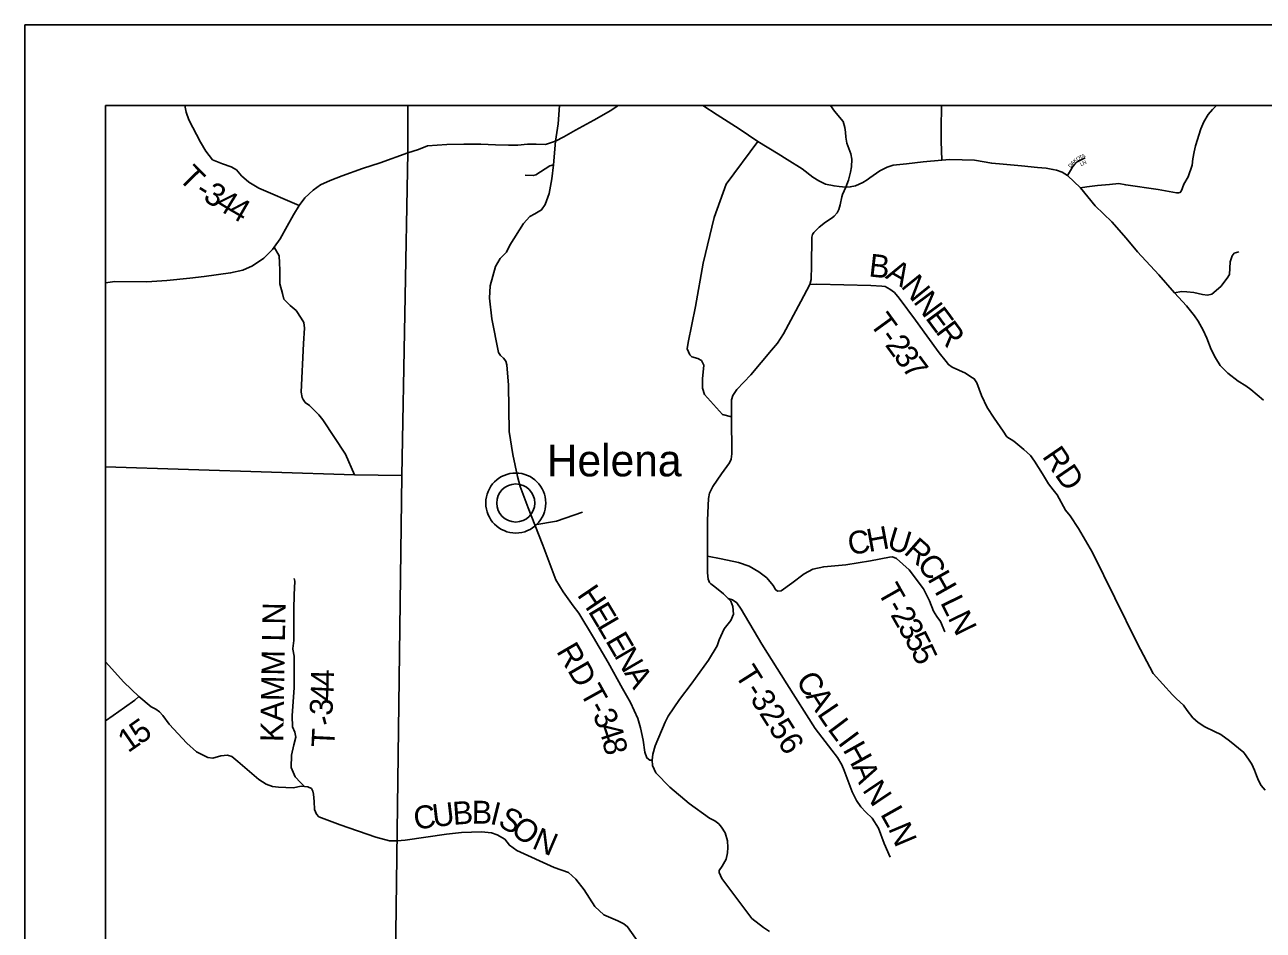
# Model space of a CAD drawing. Extents: x -22 to 431, y -18 to 160.
# Drawn here: x 319.355 to 322.427, y 157.874 to 160.12 of the extents above; entities that cross this region are included whole.
import ezdxf

# ---------------------------------------------------------------- set-up
doc = ezdxf.new("R2010")
doc.units = 0
for name, color, linetype in [('GM_X_Adjacent_County', 7, 'Continuous'), ('GM_X_Adjacent_County_Text', 7, 'Continuous'), ('GM_X_City_Street', 7, 'Continuous'), ('GM_X_City_Street_Text', 7, 'Continuous'), ('GM_X_County_Road', 7, 'Continuous'), ('GM_X_County_ROW', 7, 'Continuous'), ('GM_X_County_Subdivision', 7, 'Continuous'), ('GM_X_Major_River_Text', 7, 'Continuous'), ('GM_X_Minor_River_Text', 7, 'Continuous'), ('GM_X_Section', 7, 'Continuous'), ('GM_X_Township_Road', 7, 'Continuous'), ('GM_X_Township_ROW', 7, 'Continuous')]:
    doc.layers.add(name, color=color, linetype=linetype)

msp = doc.modelspace()

# ---------------------------------------------------------------- linework, layer by layer
at = {"layer": 'GM_X_Adjacent_County_Text'}
for points in [[(321.3912, 159.7168), (321.3982, 159.7343), (321.4032, 159.754), (321.4058, 159.7677), (321.4061, 159.7864), (321.4038, 159.7995), (321.3938, 159.8264), (321.3912, 159.8413), (321.3906, 159.8535), (321.3892, 159.8653), (321.3848, 159.8797), (321.3635, 159.9054), (321.3533, 159.9199)], [(320.9114, 158.2958), (320.9126, 158.3105), (320.9187, 158.331), (320.9431, 158.39), (320.951, 158.4051), (320.9791, 158.4459), (321.0076, 158.4841), (321.0508, 158.5438), (321.0721, 158.579), (321.0775, 158.5941), (321.0893, 158.6217), (321.1059, 158.6422), (321.1124, 158.6577), (321.1114, 158.677), (321.1061, 158.6903), (321.0992, 158.697), (321.0877, 158.7082), (321.0666, 158.7257), (321.0568, 158.7329), (321.053, 158.7363), (321.05, 158.7447), (321.0485, 158.7606), (321.0486, 158.8015), (321.0486, 158.891), (321.0507, 158.9448), (321.0534, 158.9584), (321.0613, 158.9747), (321.083, 159.0057), (321.1027, 159.0333), (321.1073, 159.0427), (321.1088, 159.056), (321.1078, 159.1478), (321.1074, 159.1894), (321.1112, 159.2004), (321.1214, 159.2148), (321.1555, 159.2514), (321.2071, 159.313), (321.2216, 159.3301), (321.2366, 159.3531), (321.2796, 159.4337), (321.3018, 159.4755), (321.3056, 159.4883), (321.3061, 159.5229), (321.3073, 159.5927), (321.309, 159.5993), (321.3122, 159.6047), (321.3252, 159.6179), (321.3409, 159.6302), (321.3576, 159.6412), (321.3628, 159.6453), (321.3699, 159.6536), (321.3737, 159.6616), (321.3773, 159.6733), (321.3815, 159.6931), (321.3832, 159.6986), (321.3912, 159.7168)], [(320.2612, 158.0954), (320.2598, 158.0954), (320.2255, 158.1044), (320.1373, 158.1353), (320.0843, 158.1549), (320.0783, 158.1614), (320.0737, 158.1735), (320.0723, 158.1933), (320.0712, 158.2115), (320.0693, 158.2191), (320.0659, 158.2251), (320.0569, 158.2297), (320.0484, 158.2306), (320.0406, 158.2309), (320.0202, 158.2272), (319.9843, 158.2285), (319.9695, 158.2304), (319.954, 158.2365), (319.9355, 158.2476), (319.8831, 158.2922), (319.8688, 158.3051), (319.8578, 158.3078), (319.8415, 158.3063), (319.8215, 158.3011), (319.8086, 158.3027), (319.7807, 158.3168), (319.7569, 158.3377), (319.7132, 158.3849), (319.697, 158.4062), (319.6887, 158.4157), (319.68, 158.4222), (319.6683, 158.4283), (319.638, 158.4533), (319.6007, 158.4889), (319.5549, 158.5394)], [(321.2019, 157.8711), (321.1868, 157.881), (321.1586, 157.9031), (321.0841, 158.0019), (321.077, 158.0174), (321.0774, 158.0224), (321.085, 158.0326), (321.0949, 158.0499), (321.0976, 158.0662), (321.0984, 158.0791), (321.0981, 158.0958), (321.0917, 158.1151), (321.0831, 158.1296), (321.0767, 158.1375), (321.0661, 158.1452), (321.0533, 158.152), (321.0024, 158.1882), (320.955, 158.2289), (320.92, 158.2643), (320.9121, 158.2829), (320.9114, 158.2958)], [(320.9623, 157.7227), (320.8499, 157.8826), (320.8409, 157.8899), (320.8258, 157.8971), (320.7911, 157.9124), (320.7685, 157.933), (320.7426, 157.974), (320.7219, 158.0009), (320.7034, 158.0169), (320.6683, 158.0296), (320.5751, 158.0719), (320.5571, 158.0848), (320.5453, 158.0994), (320.5267, 158.1106), (320.5121, 158.1157), (320.4879, 158.1179), (320.4379, 158.1162), (320.4008, 158.1123), (320.2986, 158.0977), (320.2783, 158.0954), (320.2612, 158.0954)]]:
    msp.add_lwpolyline(points, dxfattribs=at)
at = {"layer": 'GM_X_County_Road'}
for points in [[(321.0241, 159.2918), (321.0095, 159.2963), (321.0046, 159.3009), (320.9982, 159.3161), (321.0002, 159.3316), (321.0182, 159.421), (321.0378, 159.5286), (321.0646, 159.6418), (321.0947, 159.7247), (321.1732, 159.8304)], [(320.1723, 159.0038), (320.15, 159.0549), (320.0942, 159.1397), (320.0843, 159.1525), (320.0694, 159.1672), (320.0613, 159.1751), (320.0507, 159.1833), (320.0453, 159.1901), (320.0426, 159.195), (320.0402, 159.2086), (320.046, 159.3297), (320.0487, 159.3673), (320.0474, 159.3814), (320.0405, 159.3923), (320.0278, 159.4108), (320.0133, 159.4232), (319.9976, 159.439), (319.9939, 159.4534)]]:
    msp.add_lwpolyline(points, dxfattribs=at)
at = {"layer": 'GM_X_County_ROW'}
for points in [[(319.5549, 159.4802), (319.5781, 159.4828), (319.6574, 159.482), (319.707, 159.4859), (319.7643, 159.4915), (319.7997, 159.4959), (319.8652, 159.5044), (319.8958, 159.5113), (319.9195, 159.5218), (319.9481, 159.5411), (319.9691, 159.5622), (319.9732, 159.568), (319.9881, 159.589), (320.0055, 159.62), (320.021, 159.6483), (320.0355, 159.672), (320.0497, 159.6904), (320.0703, 159.7096), (320.0883, 159.7228), (320.112, 159.734), (320.1422, 159.7454), (320.1924, 159.7631), (320.2362, 159.7777), (320.3047, 159.8021), (320.3312, 159.8106), (320.3541, 159.8196), (320.3779, 159.8214), (320.4021, 159.8232), (320.4439, 159.8236), (320.4861, 159.8241), (320.5224, 159.8218), (320.5547, 159.8214), (320.5781, 159.8214), (320.6019, 159.8236), (320.623, 159.8241), (320.6464, 159.8231), (320.6709, 159.8314), (320.6917, 159.8419), (320.721, 159.8582), (320.7662, 159.8834), (320.8087, 159.9074), (320.8238, 159.9181), (320.8269, 159.9199)], [(321.0363, 159.9199), (321.0723, 159.8962), (321.1269, 159.8615), (321.1732, 159.8304), (321.2232, 159.7994), (321.2455, 159.7854), (321.2827, 159.7622), (321.3092, 159.7419), (321.3241, 159.7324), (321.3409, 159.7246), (321.3623, 159.72), (321.3749, 159.7191), (321.3912, 159.7168), (321.4022, 159.7177), (321.4153, 159.7206), (321.4332, 159.729), (321.4443, 159.7355), (321.4509, 159.74), (321.4755, 159.7573), (321.4937, 159.7671), (321.5084, 159.7716), (321.5422, 159.7753), (321.5831, 159.7802), (321.6294, 159.7839), (321.6493, 159.7856), (321.7106, 159.7839), (321.7531, 159.7764), (321.782, 159.774), (321.8273, 159.77), (321.8668, 159.7662), (321.8881, 159.7639), (321.9048, 159.7613), (321.9135, 159.7596), (321.9283, 159.7543), (321.9413, 159.7457), (321.9732, 159.7151), (322.0096, 159.6709), (322.0509, 159.6307), (322.0864, 159.5908), (322.1146, 159.5566), (322.1673, 159.4995), (322.2066, 159.4552), (322.2364, 159.4225), (322.2558, 159.3982), (322.2653, 159.3845), (322.278, 159.362), (322.2867, 159.3426), (322.2979, 159.3148), (322.3081, 159.2939), (322.3198, 159.2749), (322.3388, 159.2559), (322.3641, 159.2359), (322.3831, 159.2242), (322.3958, 159.2149), (322.427, 159.1889)]]:
    msp.add_lwpolyline(points, dxfattribs=at)
at = {"layer": 'GM_X_Major_River_Text'}
for p, q in [((320.3047, 159.8021), (320.3047, 159.9199)), ((320.2903, 159.002), (320.3047, 159.8021)), ((319.5549, 159.0232), (320.1723, 159.0038)), ((320.1723, 159.0038), (320.2903, 159.002)), ((320.2612, 156.8025), (320.2903, 159.002))]:
    msp.add_line(p, q, dxfattribs=at)
at = {"layer": 'GM_X_Minor_River_Text'}
for points in [[(320.0355, 159.672), (319.9356, 159.7147), (319.9109, 159.7296), (319.8926, 159.7454), (319.88, 159.7597), (319.8667, 159.7675), (319.845, 159.7746), (319.8207, 159.785), (319.8042, 159.8068), (319.7911, 159.8287), (319.7614, 159.8842), (319.7548, 159.9028), (319.7517, 159.9199)], [(320.6709, 159.8314), (320.6777, 159.8739), (320.6809, 159.9199)], [(321.6294, 159.7839), (321.6278, 159.8313), (321.6278, 159.863), (321.6288, 159.919), (321.6289, 159.9199)], [(321.9732, 159.7151), (321.989, 159.7179), (322.0154, 159.7212), (322.0451, 159.7237), (322.0688, 159.7258), (322.0858, 159.7226), (322.1664, 159.7112), (322.2116, 159.7033), (322.2169, 159.7031), (322.2208, 159.7042), (322.2243, 159.7089), (322.2257, 159.7126), (322.2266, 159.7158), (322.2296, 159.7249), (322.2407, 159.7424), (322.2506, 159.7713), (322.2523, 159.7871), (322.2555, 159.805), (322.2587, 159.8195), (322.2718, 159.8614), (322.2794, 159.8788), (322.2902, 159.8971), (322.3004, 159.9099), (322.3111, 159.9197), (322.3114, 159.9199)], [(320.9114, 158.2958), (320.9053, 158.2958), (320.8978, 158.3015), (320.8929, 158.3159), (320.8885, 158.3451), (320.8818, 158.3762), (320.8751, 158.399), (320.8571, 158.4384), (320.8372, 158.4738), (320.8015, 158.5379), (320.7651, 158.6002), (320.7294, 158.6602), (320.7151, 158.6788), (320.6903, 158.713), (320.6723, 158.7434), (320.6397, 158.8288), (320.6199, 158.8795), (320.6033, 158.9218), (320.5839, 158.9746), (320.5772, 158.9992), (320.5652, 159.0542), (320.5567, 159.1107), (320.5545, 159.2256), (320.5505, 159.2768), (320.5482, 159.2855), (320.5426, 159.2931), (320.5351, 159.2996), (320.5298, 159.3068), (320.5131, 159.3903), (320.5072, 159.4419), (320.5092, 159.4722), (320.5221, 159.5203), (320.5339, 159.54), (320.5495, 159.5562), (320.5578, 159.5736), (320.5916, 159.6266), (320.6075, 159.6443), (320.6196, 159.6511), (320.6367, 159.6605), (320.6458, 159.6741), (320.6557, 159.7014), (320.6622, 159.7377), (320.6662, 159.7726), (320.6709, 159.8314)], [(320.5958, 159.7471), (320.6162, 159.7459), (320.6226, 159.7474), (320.6457, 159.7625), (320.657, 159.77), (320.6662, 159.7726)], [(319.9939, 159.4534), (319.9877, 159.4772), (319.9874, 159.5114), (319.9864, 159.5296), (319.9855, 159.5466), (319.9732, 159.568)], [(322.2066, 159.4552), (322.2241, 159.458), (322.2375, 159.4574), (322.2541, 159.4561), (322.2762, 159.4511), (322.2883, 159.4492), (322.2992, 159.4514), (322.3216, 159.4708), (322.3371, 159.491), (322.3431, 159.5003), (322.3443, 159.532), (322.3498, 159.5471), (322.3547, 159.553), (322.3665, 159.5565)], [(321.3018, 159.4755), (321.3192, 159.4764), (321.4531, 159.4734), (321.4808, 159.4712), (321.4893, 159.4704), (321.5004, 159.464), (321.5119, 159.4555), (321.5238, 159.4414), (321.5643, 159.3868), (321.592, 159.3485), (321.6228, 159.3062), (321.6399, 159.2843), (321.6459, 159.2771), (321.6552, 159.271), (321.6878, 159.256), (321.7017, 159.2467), (321.7098, 159.2418), (321.7164, 159.2318), (321.7282, 159.2001), (321.7415, 159.1706), (321.759, 159.1438), (321.7814, 159.112), (321.7903, 159.0981), (321.808, 159.0867), (321.8329, 159.0664), (321.8493, 159.0512), (321.859, 159.0373), (321.879, 159.0063), (321.8942, 158.9809), (321.9058, 158.9666), (321.9154, 158.9537), (321.936, 158.9157), (321.9477, 158.9021), (321.9682, 158.8701), (322.0033, 158.8107), (322.1137, 158.5863), (322.1538, 158.5111), (322.2012, 158.4579), (322.2105, 158.449), (322.221, 158.4398), (322.2292, 158.4321), (322.2381, 158.4192), (322.2518, 158.4008), (322.2649, 158.3889), (322.2814, 158.3781), (322.3058, 158.3665), (322.3212, 158.3591), (322.3433, 158.3433), (322.3784, 158.3144), (322.3918, 158.2961), (322.3981, 158.2858), (322.4047, 158.2713), (322.4099, 158.2576), (322.4146, 158.2454), (322.4217, 158.2325), (322.4313, 158.221)], [(321.1078, 159.1478), (321.0857, 159.1535), (321.0409, 159.2029), (321.0357, 159.2189), (321.0361, 159.242), (321.0393, 159.2754), (321.0336, 159.2871), (321.0246, 159.2917), (321.0241, 159.2918)], [(320.6199, 158.8795), (320.6739, 158.8882), (320.7378, 158.9107)], [(321.0486, 158.8015), (321.0819, 158.7953), (321.1249, 158.7857), (321.1517, 158.7769), (321.1755, 158.7628), (321.1951, 158.7479), (321.2109, 158.7289), (321.2165, 158.719), (321.2218, 158.7152), (321.2312, 158.7156), (321.2574, 158.7352), (321.2876, 158.7582), (321.3092, 158.7695), (321.3364, 158.7755), (321.3912, 158.7802), (321.4524, 158.7902), (321.4997, 158.7995), (321.5072, 158.7998), (321.5167, 158.7956), (321.5487, 158.7682), (321.584, 158.7211), (321.5991, 158.6911), (321.6088, 158.6657), (321.6167, 158.6524), (321.6261, 158.6395), (321.6373, 158.6144)], [(320.02, 158.5729), (320.0219, 158.5923), (320.0221, 158.6378), (320.0222, 158.6705), (320.0229, 158.7061), (320.0248, 158.7399), (320.0232, 158.746)], [(321.501, 158.0549), (321.4863, 158.089), (321.4721, 158.1274), (321.4563, 158.1517), (321.4409, 158.1665), (321.4285, 158.1802), (321.418, 158.1961), (321.4071, 158.2174), (321.397, 158.244), (321.3869, 158.2701), (321.3816, 158.2838), (321.3704, 158.302), (321.3568, 158.3203), (321.3154, 158.3742), (321.2448, 158.4848), (321.1828, 158.5839), (321.1321, 158.6705), (321.1212, 158.6857), (321.1099, 158.6933), (321.0992, 158.697)], [(320.0484, 158.2306), (320.0388, 158.2405), (320.0255, 158.2544), (320.0154, 158.2774), (320.0162, 158.3085), (320.0224, 158.3336), (320.0274, 158.353), (320.0243, 158.3651), (320.0189, 158.3787), (320.0182, 158.406), (320.0231, 158.4759), (320.023, 158.524), (320.0234, 158.5536), (320.0198, 158.5714), (320.0199, 158.5725), (320.02, 158.5729)], [(319.5549, 158.3931), (319.5745, 158.4066), (319.6025, 158.4263), (319.6275, 158.4448), (319.638, 158.4533)]]:
    msp.add_lwpolyline(points, dxfattribs=at)
at = {"layer": 'GM_X_Section'}
for p, q in [((319.5549, 159.9199), (331.7949, 159.9199)), ((319.5549, 147.6799), (319.5549, 159.9199))]:
    msp.add_line(p, q, dxfattribs=at)
msp.add_lwpolyline([(319.3549, 160.1199), (331.9949, 160.1199), (331.9949, 147.4799), (319.3549, 147.4799)], close=True, dxfattribs=at)
at = {"layer": 'GM_X_Township_Road'}
for radius in [0.0744, 0.0472]:
    msp.add_circle((320.5727, 158.9336), radius, dxfattribs=at)
at = {"layer": 'GM_X_Township_ROW'}
msp.add_lwpolyline([(321.9413, 159.7457), (321.9485, 159.7585), (321.9544, 159.7681), (321.9592, 159.7744), (321.9649, 159.7796), (321.9738, 159.7844), (321.9849, 159.7896)], dxfattribs=at)

# ---------------------------------------------------------------- texts
at = {"layer": 'GM_X_Adjacent_County'}
msp.add_text('Helena', height=0.07891, rotation=0, dxfattribs=at).set_placement((320.6495, 158.9998))
at = {"layer": 'GM_X_City_Street'}
for s, rotation, p in [('C', 7.1652, (320.3228, 158.1234)), ('U', 6.9732, (320.369, 158.1292)), ('B', 4.2444, (320.4179, 158.1352)), ('B', 359.237, (320.4632, 158.1386)), ('I', 346.102, (320.5064, 158.1384)), ('S', 331.2181, (320.5255, 158.1342)), ('O', 322.1589, (320.5571, 158.1171)), ('N', 336.9026, (320.6103, 158.0783))]:
    msp.add_text(s, height=0.0568, rotation=rotation, dxfattribs=at).set_placement(p)
at = {"layer": 'GM_X_City_Street_Text'}
for s, height, rotation, p in [('T', 0.0568, 314.3333, (319.7334, 159.7379)), ('-', 0.0568, 328.0219, (319.7746, 159.6982)), ('3', 0.0568, 328.2589, (319.7946, 159.6857)), ('4', 0.0568, 328.4651, (319.8246, 159.6672)), ('4', 0.0568, 329.907, (319.8558, 159.6481)), ('B', 0.0568, 353.4796, (321.4466, 159.496)), ('A', 0.0568, 329.8469, (321.4871, 159.4927)), ('N', 0.0568, 308.8669, (321.5262, 159.4711)), ('N', 0.0568, 306.5373, (321.5572, 159.4327)), ('T', 0.0568, 305.9883, (321.4484, 159.379)), ('E', 0.0568, 306.4928, (321.587, 159.3925)), ('R', 0.0568, 306.5076, (321.6123, 159.3583)), ('2', 0.0568, 306.0117, (321.4871, 159.3257)), ('-', 0.0568, 305.9855, (321.4734, 159.3446)), ('3', 0.0568, 306.0998, (321.5078, 159.2973)), ('7', 0.0568, 306.4674, (321.5286, 159.2687)), ('RD', 0.05682, 304.5091, (321.8769, 159.0492)), ('H', 0.0568, 10.409, (321.4484, 158.8118)), ('U', 0.0568, 343.1301, (321.4905, 158.8212)), ('C', 0.0568, 9.0459, (321.4008, 158.8042)), ('R', 0.0568, 318.6801, (321.5328, 158.8098)), ('C', 0.0568, 307.0736, (321.5657, 158.7812)), ('H', 0.0568, 299.4652, (321.5928, 158.7456)), ('H', 0.0568, 304.1255, (320.7231, 158.7057)), ('T', 0.0568, 299.5966, (321.4684, 158.714)), ('E', 0.0568, 300.9707, (320.7507, 158.665)), ('L', 0.0568, 296.1348, (321.6248, 158.6872)), ('KAMM LN', 0.05682, 89.0064, (319.9958, 158.3404)), ('2', 0.0568, 299.6869, (321.5009, 158.6567)), ('-', 0.0568, 299.6177, (321.4894, 158.677)), ('N', 0.0568, 296.1219, (321.6435, 158.649)), ('L', 0.0568, 300.235, (320.7725, 158.6288)), ('3', 0.0568, 300.422, (321.5187, 158.6256)), ('E', 0.0568, 300.2339, (320.7939, 158.5921)), ('5', 0.0568, 297.2016, (321.536, 158.5962)), ('RD', 0.05682, 300.1559, (320.6721, 158.5662)), ('N', 0.0568, 300.2297, (320.8153, 158.5553)), ('5', 0.0568, 295.6271, (321.5518, 158.5654)), ('T-3256', 0.05682, 302.327, (321.1144, 158.5084)), ('4', 0.0568, 89.4173, (320.1215, 158.4785)), ('A', 0.0568, 300.2295, (320.8405, 158.5121)), ('C', 0.0568, 302.4462, (321.2657, 158.4936)), ('4', 0.0568, 87.0096, (320.1196, 158.441)), ('T', 0.0568, 299.0708, (320.7304, 158.464)), ('3', 0.0568, 86.1461, (320.1172, 158.4051)), ('A', 0.0568, 302.5613, (321.2908, 158.4541)), ('3', 0.0568, 296.1822, (320.7619, 158.407)), ('-', 0.0568, 298.6478, (320.751, 158.4269)), ('L', 0.0568, 304.2106, (321.3187, 158.4104)), ('5', 0.0568, 35.2841, (319.6404, 158.333)), ('-', 0.0568, 104.3905, (320.1225, 158.3873)), ('4', 0.0568, 288.1898, (320.7766, 158.3776)), ('L', 0.0568, 306.9844, (321.3443, 158.3729)), ('1', 0.0568, 34.6697, (319.611, 158.3127)), ('T', 0.0568, 87.2175, (320.1224, 158.3264)), ('8', 0.0568, 281.9728, (320.7871, 158.3459)), ('I', 0.0568, 306.7528, (321.3699, 158.3389)), ('H', 0.0568, 299.1195, (321.3827, 158.3219)), ('A', 0.0568, 291.5795, (321.4062, 158.28)), ('N', 0.0568, 303.9219, (321.4308, 158.2217)), ('L', 0.0568, 299.3845, (321.4757, 158.1621)), ('N', 0.0568, 292.8669, (321.4958, 158.1266))]:
    msp.add_text(s, height=height, rotation=rotation, dxfattribs=at).set_placement(p)
at = {"layer": 'GM_X_County_Subdivision'}
for s, rotation, p in [('T', 25.1968, (321.9728, 159.7856)), ('A', 24.3653, (321.9788, 159.7884)), ('D', 54.1815, (321.9493, 159.7645)), ('A', 46.4454, (321.954, 159.771)), ('K', 37.9497, (321.9594, 159.7767)), ('O', 28.6375, (321.9657, 159.7816)), ('L', 28.9365, (321.9753, 159.7687)), ('N', 27.0831, (321.9811, 159.7718))]:
    msp.add_text(s, height=0.00947, rotation=rotation, dxfattribs=at).set_placement(p)

doc.saveas('drawing.dxf')
